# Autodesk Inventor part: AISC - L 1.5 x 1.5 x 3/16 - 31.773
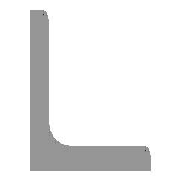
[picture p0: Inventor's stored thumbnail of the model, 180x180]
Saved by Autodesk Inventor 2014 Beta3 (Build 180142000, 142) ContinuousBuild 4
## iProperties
_CCFamilyMember: 5
_CCFamilyDisplayName: ANSI L (Equal angles) - Angle Steel
_FrameMemberDoc: Frame Member File
_Version: 15.0.0
_GetPNFromCC: 1
Created: 2010-11
Part Number: AISC - L 1.5 x 1.5 x 3/16 - 31.773
Material: Steel, Mild
Description: Angle Steel
Document SubType Name: Modeling
Standard: ANSI
Designer: Beta-8540w
Standards Organization: ANSI
Language: en-US
Size Designation: L 1.5 x 1.5 x 3/16
Categories: <MemberInstance><Categories><Category DisplayName="Structural Shapes" InternalName="089c4875-fa83-4c05-b084-43b9cc11f5ed" Mnemonic="GRDR"><CategoryParameter Dis
Stock Number: L 1.5 x 1.5 x 3/16
Density: 7.86 g/cm^3
Appearance: Steel
IsCustomPart: 1
G_L: 31.773 in
G_W: 1.500 in
G_H: 1.500 in
+3B2E30B5-4963-484D-8D95-D946A704ABD9+CUTDETAIL1: Cut
Author: Beta-8540w
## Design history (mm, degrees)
node "Start plane"
node "End plane"
sketch "Sketch"
  geometry: L1 (38.1, 0)-(0, 0); L2 (0, 0)-(0, 38.1); L3 (0, 38.1)-(2.476, 38.1); L4 (4.762, 35.814)-(4.762, 9.589); L5 (9.588, 4.763)-(35.814, 4.763); L6 (38.1, 2.477)-(38.1, 0); L7 (0, -11.041)-(0, 31.538); L8 (-11.041, 0)-(31.538, 0); L9 (0, 48.496)-(0, -20.964) reference; L10 (-20.964, 0)-(48.496, 0) reference; A1 r 4.826 centre (9.588, 9.589) between (4.762, 9.589) and (9.588, 4.763); A2 r 2.286 centre (2.476, 35.814) between (4.762, 35.814) and (2.476, 38.1); A3 r 2.286 centre (35.814, 2.477) between (38.1, 2.477) and (35.814, 4.763); 3 further points
  constraints: 16 end point, 6 point on circle, 6 point on line, 6 tangent, 4 parallel, 3 centre point, 2 collinear, 1 equal radius, 1 horizontal, 1 perpendicular
  dimensions: "d0" = 38.1 distance between parallel lines of L6 L2 (= G_H); "d1" = 38.1 distance between parallel lines of L3 L1 (= G_H); "d2" = 4.7625 distance between parallel lines of L2 L4 (= G_T); "d3" = 4.7625 distance between parallel lines of L1 L5 (= G_T); "d10" = 0 distance between parallel lines of L7 L2 (computed from ex); "d11" = 0 distance between parallel lines of L8 L1 (computed from d10); "d14" = 4.826 radius of A1 (= G_IR); "d15" = 2.286 radius of A2 (= G_ER)
extrude "Body" new body sketch "Sketch" stored distance "d4" = 807.03543 (= G_L); taper "d5" = 0 deg
node "Driven Length"
  sketch "Sketch3"
    geometry: L1 (0, 0)-(10, 0) reference
    constraints: 2 end point, 1 horizontal
  workplane "Work Plane3"
  sketch "Sketch4"
    geometry: L1 (-2, 0)-(12, 0) reference; L2 (-2, 807.035)-(12, 807.035) reference
    dimensions: "d17" = 807.03543 distance between parallel lines of L1 L2 (derived)
workplane "Work Plane4"
split "Split1"
body "Solid1"
other parameters: "G_H" = 38.1 [user parameter; used in 2 equation terms], "G_T" = 4.7625 [user parameter; used in 2 equation terms], "G_ER" = 2.286 [user parameter; used in 1 equation term], "G_IR" = 4.826 [user parameter; used in 1 equation term], "G_L" = 807.03543 (= d17) [user parameter; used in 1 equation term], "ex" = 0 [user parameter; used in 1 equation term], "G_OFFSET_START" = 0 [user parameter; used in 1 equation term], "G_OFFSET_END" = -29.72999 [user parameter; used in 1 equation term], "d12" = 0 (computed from G_OFFSET_START), "d13" = 807.03543 (= G_OFFSET_END + B_L), "B_L" = 836.76542 [user parameter; used in 1 equation term], "d16" = 90 deg, "MAS" = 0.26787 [user parameter]
